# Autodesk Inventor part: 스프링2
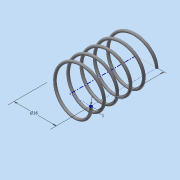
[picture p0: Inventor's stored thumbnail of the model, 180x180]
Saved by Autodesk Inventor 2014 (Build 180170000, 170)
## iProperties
Created: 2015-06
Part Number: 스프링2
Material: 강철, 연강
Document SubType Name: Modeling
Designer: MYHOME
Density: 1 g/cm^3
Appearance: 강철
Mass: 0.195337 g
Surface Area: 7.89042 cm^2
Volume: 0.195337 cm^3
Author: MYHOME
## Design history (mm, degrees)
sketch "스케치1"
  geometry: L1 (0, 0)-(8, 0); L2 (8, 0)-(8, 21.5); L3 (8, 21.5)-(0, 21.5); L4 (0, 21.5)-(0, 0); C1 r 0.5 at (8, 0)
  constraints: 8 end point, 2 parallel, 1 centre point, 1 coincident, 1 horizontal, 1 perpendicular
  dimensions: "d0" = 16 diameter of L2 L4; "d1" = 21.5 distance of L1.end L2.end (derived); "d2" = 1 diameter of C1
feature "코일1" sketch "스케치1" pitch "d3" = 10; turns "d5" = 5; dims "d4" = 21.5 (= d1), "d6" = 0, angle "d7" = 90 deg, angle "d8" = 90 deg, "d9" = 0, "d10" = 0
node "작업 평면1"
sketch "스케치2"
  geometry: L1 (-8.5, 0)-(-7.5, 0) reference; 1 further point
  constraints: 1 horizontal alignment
extrude "돌출1" cut sketch "스케치2" stored distance "d12" = 10; taper "d13" = 0 deg
node "작업 평면2"
sketch "스케치3"
  geometry: L1 (8.5, 0)-(7.5, 0) reference; 1 further point
  constraints: 1 horizontal alignment
extrude "돌출2" cut sketch "스케치3" stored distance "d15" = 10; taper "d16" = 0 deg
node "솔리드1"
node "절단 모서리 투영1"
node "절단 모서리 투영2"
other parameters: "d11" = 0, "d14" = -21.5 (= -d1)
